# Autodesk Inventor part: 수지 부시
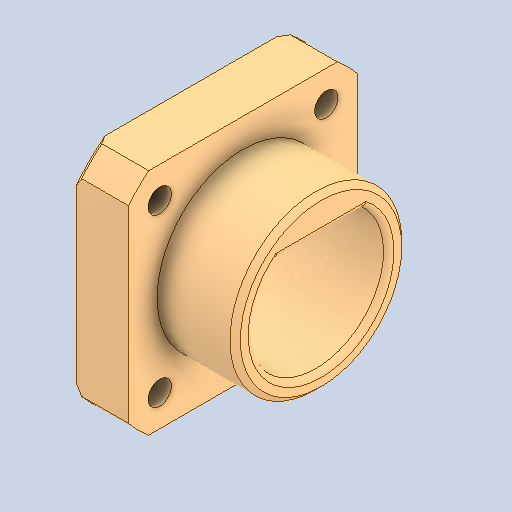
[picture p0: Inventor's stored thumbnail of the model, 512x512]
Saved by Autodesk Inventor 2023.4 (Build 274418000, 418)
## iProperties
Created: 2024-10
Part Number: 수지 부시
Material: ABS 플라스틱
Document SubType Name: Modeling
Designer: EDU
Density: 1.06 g/cm^3
Appearance: 기본값
Author: jhkim
Sending System: Autodesk Inventor 2025
Preprocessor: ST-DEVELOPER v20
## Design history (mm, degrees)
feature "솔리드1"
node "솔리드2"
